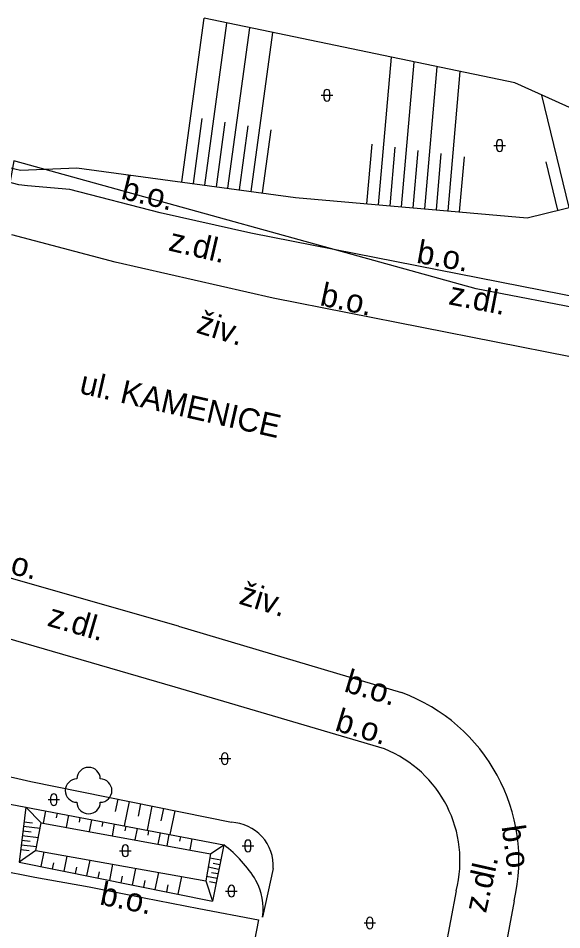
# Model space of a CAD drawing. Extents: x -601602 to -600882, y -1162594 to -1161950.
# Drawn here: x -601531.37 to -601508.03, y -1162301.67 to -1162262.51 of the extents above; entities that cross this region are included whole.
import ezdxf

# ---------------------------------------------------------------- set-up
doc = ezdxf.new("R2010")
doc.units = 0
for name, color, linetype in [('VRSTVA 1', 7, 'Continuous'), ('Vrstva 13', 7, 'Continuous'), ('Vrstva 14', 7, 'Continuous'), ('Vrstva 15 (Construction)', 7, 'Continuous'), ('Vrstva 16', 7, 'Continuous')]:
    doc.layers.add(name, color=color, linetype=linetype)

msp = doc.modelspace()

# ---------------------------------------------------------------- linework, layer by layer
at = {"layer": 'VRSTVA 1'}
msp.add_lwpolyline([(-601331.31, -1162306.58), (-601332.3, -1162306.37), (-601334.05, -1162306.03), (-601365.21, -1162299.85), (-601405.05, -1162291.66), (-601414.46, -1162290.57), (-601424.01, -1162291.3), (-601452.18, -1162285.72), (-601481.36, -1162280.32), (-601487.9, -1162279.02), (-601506.8, -1162275.08), (-601511.71, -1162274.13), (-601531.56, -1162268.63), (-601534.84, -1162286.8), (-601535.95, -1162290.68)], dxfattribs=at)
at = {"layer": 'Vrstva 13'}
for p, q in [((-601531.35, -1162269.67), (-601533.55, -1162269.07)), ((-601530.98, -1162269.71), (-601531.35, -1162269.67)), ((-601529.16, -1162269.87), (-601530.98, -1162269.71)), ((-601525.28, -1162270.87), (-601529.16, -1162269.87)), ((-601521.39, -1162271.75), (-601525.28, -1162270.87)), ((-601504.73, -1162275.03), (-601521.39, -1162271.75)), ((-601527.21, -1162272.99), (-601531.65, -1162271.82)), ((-601520.42, -1162274.54), (-601527.21, -1162272.99)), ((-601507.65, -1162277.05), (-601520.42, -1162274.54)), ((-601524.49, -1162288.62), (-601540.6, -1162284.04)), ((-601524.63, -1162291.24), (-601539.35, -1162286.98)), ((-601524.49, -1162288.62), (-601514.92, -1162291.48)), ((-601515.65, -1162293.9), (-601524.63, -1162291.24)), ((-601532.99, -1162298.95), (-601530.66, -1162299.41)), ((-601530.66, -1162299.41), (-601528.32, -1162299.82)), ((-601528.32, -1162299.82), (-601525.97, -1162300.29)), ((-601512.57, -1162299.99), (-601513.69, -1162305.98)), ((-601525.97, -1162300.29), (-601523.61, -1162300.75)), ((-601523.61, -1162300.75), (-601521.05, -1162301.24)), ((-601510.07, -1162300.42), (-601510.62, -1162303.36)), ((-601521.05, -1162301.24), (-601521.67, -1162304.41))]:
    msp.add_line(p, q, dxfattribs=at)
for centre, radius, start, end in [((-601517.552, -1162298.693), 7.679, 347.0057, 69.9544), ((-601517.56, -1162298.69), 5.157, 345.3997, 68.256)]:
    msp.add_arc(centre, radius, start, end, dxfattribs=at)
at = {"layer": 'Vrstva 14'}
for p, q in [((-601524.348, -1162269.544), (-601523.39, -1162262.51)), ((-601510.05, -1162265.29), (-601523.39, -1162262.51)), ((-601523.357, -1162269.679), (-601522.409, -1162262.715)), ((-601522.366, -1162269.814), (-601521.427, -1162262.919)), ((-601521.375, -1162269.949), (-601520.446, -1162263.124)), ((-601515.905, -1162270.521), (-601515.35, -1162264.185)), ((-601514.909, -1162270.608), (-601514.365, -1162264.391)), ((-601513.912, -1162270.696), (-601513.378, -1162264.596)), ((-601512.916, -1162270.783), (-601512.393, -1162264.802)), ((-601501.55, -1162269.13), (-601510.05, -1162265.29)), ((-601518.366, -1162265.819), (-601517.866, -1162265.819)), ((-601518.241, -1162265.944), (-601518.241, -1162265.694)), ((-601517.991, -1162265.944), (-601517.991, -1162265.694)), ((-601507.712, -1162270.638), (-601508.893, -1162265.813)), ((-601523.852, -1162269.612), (-601523.471, -1162266.812)), ((-601522.862, -1162269.747), (-601522.484, -1162266.975)), ((-601521.871, -1162269.882), (-601521.497, -1162267.138)), ((-601520.88, -1162270.017), (-601520.51, -1162267.3)), ((-601510.825, -1162268.104), (-601510.825, -1162267.854)), ((-601510.575, -1162268.104), (-601510.575, -1162267.854)), ((-601516.403, -1162270.478), (-601516.179, -1162267.92)), ((-601515.407, -1162270.565), (-601515.187, -1162268.054)), ((-601514.41, -1162270.652), (-601514.195, -1162268.189)), ((-601510.95, -1162267.979), (-601510.45, -1162267.979)), ((-601533.56, -1162268.51), (-601531.28, -1162269.04)), ((-601513.414, -1162270.739), (-601513.203, -1162268.323)), ((-601512.418, -1162270.826), (-601512.211, -1162268.458)), ((-601508.198, -1162270.756), (-601508.707, -1162268.674)), ((-601531.28, -1162269.04), (-601528.86, -1162268.93)), ((-601528.86, -1162268.93), (-601519.46, -1162270.21)), ((-601509.52, -1162271.08), (-601501.55, -1162269.13)), ((-601519.46, -1162270.21), (-601509.52, -1162271.08)), ((-601539.43, -1162293.35), (-601530.83, -1162295.3)), ((-601522.749, -1162294.316), (-601522.249, -1162294.316)), ((-601522.624, -1162294.441), (-601522.624, -1162294.191)), ((-601522.374, -1162294.441), (-601522.374, -1162294.191)), ((-601530.83, -1162295.3), (-601522.22, -1162297.05)), ((-601530.094, -1162296.077), (-601529.594, -1162296.077)), ((-601529.969, -1162296.202), (-601529.969, -1162295.952)), ((-601529.719, -1162296.202), (-601529.719, -1162295.952)), ((-601527.099, -1162296.058), (-601527.207, -1162296.588)), ((-601531.95, -1162296.23), (-601522.55, -1162298.02)), ((-601531.052, -1162296.401), (-601531.33, -1162298.76)), ((-601530.39, -1162297.07), (-601531.052, -1162296.401)), ((-601526.609, -1162296.158), (-601526.822, -1162297.206)), ((-601526.119, -1162296.258), (-601526.227, -1162296.79)), ((-601525.629, -1162296.357), (-601525.839, -1162297.394)), ((-601525.139, -1162296.457), (-601525.248, -1162296.992)), ((-601530.196, -1162296.564), (-601530.296, -1162297.087)), ((-601529.705, -1162296.658), (-601529.744, -1162296.865)), ((-601529.213, -1162296.751), (-601529.311, -1162297.267)), ((-601528.722, -1162296.845), (-601528.761, -1162297.05)), ((-601524.649, -1162296.556), (-601524.857, -1162297.581)), ((-601530.437, -1162297.322), (-601531.151, -1162297.238)), ((-601530.766, -1162297.082), (-601531.128, -1162297.04)), ((-601530.61, -1162298.26), (-601530.39, -1162297.07)), ((-601530.39, -1162297.07), (-601523.11, -1162298.4)), ((-601528.231, -1162296.938), (-601528.328, -1162297.447)), ((-601527.74, -1162297.032), (-601527.778, -1162297.234)), ((-601527.249, -1162297.125), (-601527.344, -1162297.626)), ((-601526.758, -1162297.219), (-601526.796, -1162297.418)), ((-601530.509, -1162297.716), (-601531.198, -1162297.635)), ((-601530.812, -1162297.479), (-601531.174, -1162297.437)), ((-601526.266, -1162297.312), (-601526.36, -1162297.806)), ((-601525.775, -1162297.406), (-601525.812, -1162297.602)), ((-601525.284, -1162297.499), (-601525.377, -1162297.986)), ((-601524.9, -1162297.573), (-601524.992, -1162298.056)), ((-601530.582, -1162298.111), (-601531.244, -1162298.033)), ((-601530.858, -1162297.876), (-601531.22, -1162297.834)), ((-601524.408, -1162297.666), (-601524.445, -1162297.858)), ((-601523.917, -1162297.76), (-601524.008, -1162298.236)), ((-601523.11, -1162298.4), (-601522.55, -1162298.02)), ((-601522.55, -1162298.02), (-601523.03, -1162300.44)), ((-601521.633, -1162298.189), (-601521.633, -1162297.939)), ((-601521.383, -1162298.189), (-601521.383, -1162297.939)), ((-601530.61, -1162298.26), (-601531.33, -1162298.76)), ((-601530.904, -1162298.274), (-601531.266, -1162298.232)), ((-601530.61, -1162298.26), (-601523.32, -1162299.57)), ((-601530.386, -1162298.951), (-601530.259, -1162298.323)), ((-601527.023, -1162298.272), (-601526.523, -1162298.272)), ((-601526.898, -1162298.397), (-601526.898, -1162298.147)), ((-601526.648, -1162298.397), (-601526.648, -1162298.147)), ((-601523.11, -1162298.4), (-601523.32, -1162299.57)), ((-601521.758, -1162298.064), (-601521.258, -1162298.064)), ((-601531.33, -1162298.76), (-601523.03, -1162300.44)), ((-601529.896, -1162299.05), (-601529.844, -1162298.795)), ((-601529.406, -1162299.149), (-601529.275, -1162298.5)), ((-601528.426, -1162299.348), (-601528.29, -1162298.677)), ((-601523.142, -1162298.577), (-601522.679, -1162298.669)), ((-601523, -1162298.809), (-601522.718, -1162298.865)), ((-601528.916, -1162299.249), (-601528.862, -1162298.985)), ((-601527.936, -1162299.447), (-601527.881, -1162299.174)), ((-601527.446, -1162299.546), (-601527.306, -1162298.854)), ((-601526.466, -1162299.745), (-601526.321, -1162299.031)), ((-601525.485, -1162299.943), (-601525.336, -1162299.208)), ((-601523.212, -1162298.97), (-601522.757, -1162299.061)), ((-601523.078, -1162299.201), (-601522.796, -1162299.257)), ((-601520.42, -1162299.03), (-601520.88, -1162301.12)), ((-601526.956, -1162299.645), (-601526.899, -1162299.364)), ((-601525.975, -1162299.844), (-601525.917, -1162299.554)), ((-601524.505, -1162300.141), (-601524.352, -1162299.385)), ((-601523.32, -1162299.57), (-601523.03, -1162300.44)), ((-601523.283, -1162299.365), (-601522.835, -1162299.454)), ((-601523.156, -1162299.594), (-601522.874, -1162299.65)), ((-601524.995, -1162300.042), (-601524.935, -1162299.744)), ((-601522.34, -1162300.13), (-601522.34, -1162299.88)), ((-601522.09, -1162300.13), (-601522.09, -1162299.88)), ((-601522.465, -1162300.005), (-601521.965, -1162300.005)), ((-601516.523, -1162301.376), (-601516.023, -1162301.376)), ((-601516.398, -1162301.501), (-601516.398, -1162301.251)), ((-601516.148, -1162301.501), (-601516.148, -1162301.251))]:
    msp.add_line(p, q, dxfattribs=at)
msp.add_circle((-601528.35, -1162295.69), 0.0005, dxfattribs=at)
for centre, radius, start, end in [((-601518.115, -1162265.694), 0.125, 0, 180), ((-601518.115, -1162265.944), 0.125, 180, 360), ((-601510.699, -1162267.854), 0.125, 0, 180), ((-601510.699, -1162268.104), 0.125, 180, 360), ((-601522.498, -1162294.191), 0.125, 0, 180), ((-601522.498, -1162294.441), 0.125, 180, 360), ((-601528.35, -1162295.19), 0.5, 0, 180), ((-601528.85, -1162295.69), 0.5, 90, 270), ((-601527.85, -1162295.69), 0.5, 270, 90), ((-601529.844, -1162295.952), 0.125, 0, 180), ((-601529.844, -1162296.202), 0.125, 180, 360), ((-601528.35, -1162296.19), 0.5, 180, 360), ((-601522.297, -1162298.928), 1.879, 356.8805, 87.6669), ((-601526.773, -1162298.147), 0.125, 0, 180), ((-601525.609, -1162302.185), 5.167, 30.615, 53.7013), ((-601521.508, -1162297.939), 0.125, 0, 180), ((-601526.773, -1162298.397), 0.125, 180, 360), ((-601521.508, -1162298.189), 0.125, 180, 360), ((-601523.311, -1162300.749), 2.459, 351.3342, 29.1055), ((-601522.214, -1162299.88), 0.125, 0, 180), ((-601522.214, -1162300.13), 0.125, 180, 360), ((-601516.272, -1162301.251), 0.125, 0, 180), ((-601516.272, -1162301.501), 0.125, 180, 360)]:
    msp.add_arc(centre, radius, start, end, dxfattribs=at)

# ---------------------------------------------------------------- texts
at = {"layer": 'Vrstva 15 (Construction)'}
msp.add_text('ul. KAMENICE', height=1, rotation=347.2146, dxfattribs=at).set_placement((-601528.786, -1162278.613))
at = {"layer": 'Vrstva 16'}
for s, rotation, p in [('b.o.', 346.4202, (-601526.999, -1162270.255)), ('z.dl.', 346.7844, (-601524.965, -1162272.477)), ('b.o.', 349.7411, (-601514.308, -1162273.008)), ('b.o.', 347.8228, (-601518.457, -1162274.831)), ('z.dl.', 348.88, (-601512.929, -1162274.793)), ('živ.', 342.9797, (-601523.769, -1162276.005)), ('b.o.', 346.2919, (-601532.835, -1162286.106)), ('živ.', 342.9797, (-601521.938, -1162287.652)), ('z.dl.', 343.8594, (-601530.171, -1162288.595)), ('b.o.', 343.304, (-601517.422, -1162291.417)), ('b.o.', 343.304, (-601517.817, -1162293.094)), ('b.o.', 277.9518, (-601510.618, -1162297.23)), ('z.dl.', 77.3079, (-601511.289, -1162300.979)), ('b.o.', 348.6008, (-601527.913, -1162300.575))]:
    msp.add_text(s, height=1, rotation=rotation, dxfattribs=at).set_placement(p)

doc.saveas('drawing.dxf')
